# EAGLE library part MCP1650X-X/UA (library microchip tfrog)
Microchip MCP1650 : MCP1650/51/52/53 is a 750 kHz gated oscillator boost controller packaged in an 8 or 10-pin MSOP package. Developed for high-power, portable applications, the gated oscillator controller can deliver 5 watts of power to the load while consuming only 120 µA of quiescent current at no load. MCP1650/51/52/53 can operate over a wide input voltage range (2.0V to 5.5V) to accommodate multiple primary-cell and single-cell Li-Ion battery-powered applications, in addition to 2.8V, 3.3V and 5.0V regulated input voltages. Additional features integrated on the MCP1650/51/52/ 53 family include peak input current limit, adjustable output voltage/current, low battery detection and power-good indication. Doc: http://www.microchip.com/wwwproducts/Devices.aspx?dDocName=en500061 Ref Used: MCP1650S-E/MS (2.55v)
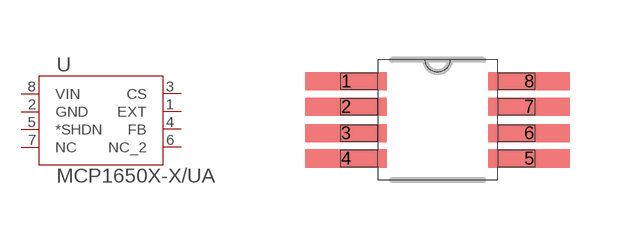
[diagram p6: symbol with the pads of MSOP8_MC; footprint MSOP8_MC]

Designator prefix -

## MCP1650X-X/UA  [MSOP8_MC]
1  EXT  pas
2  GND  pas
3  CS  pas
4  FB  pas
5  *SHDN  pas
6  NC_2  pas
7  NC  pas
8  VIN  pas

## Footprint MSOP8_MC (pad centres in mm)
MSOP8 with long pads (0.08inch instead of 0.06)
smd 2.032 x 0.457: 1 -2.286,0.965; 2 -2.286,0.33; 3 -2.286,-0.33; 4 -2.286,-0.965; 5 2.286,-0.965; 6 2.286,-0.33; 7 2.286,0.33; 8 2.286,0.965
